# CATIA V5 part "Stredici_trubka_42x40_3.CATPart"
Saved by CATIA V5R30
Part number: Stredici_trubka_42x40_3
Definition: E 1160_42x40
Nomenclature: E 1160_42x40
Source: Unknown
Description: PART--DESC
Bounding box of the stored display mesh (mm): x 166 to 208, y -157.99 to -116.01, z 90.7 to 130.7
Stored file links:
  E:\Bakalarka\Model\Forma_v7\Stredici_trubka_42x40_3.CATPart
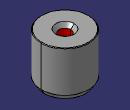
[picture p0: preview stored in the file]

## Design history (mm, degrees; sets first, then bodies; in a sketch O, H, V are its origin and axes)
Body1 "MANIFOLD_SOLID_BREP #3874" (main body)
  Solid1: solid without history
